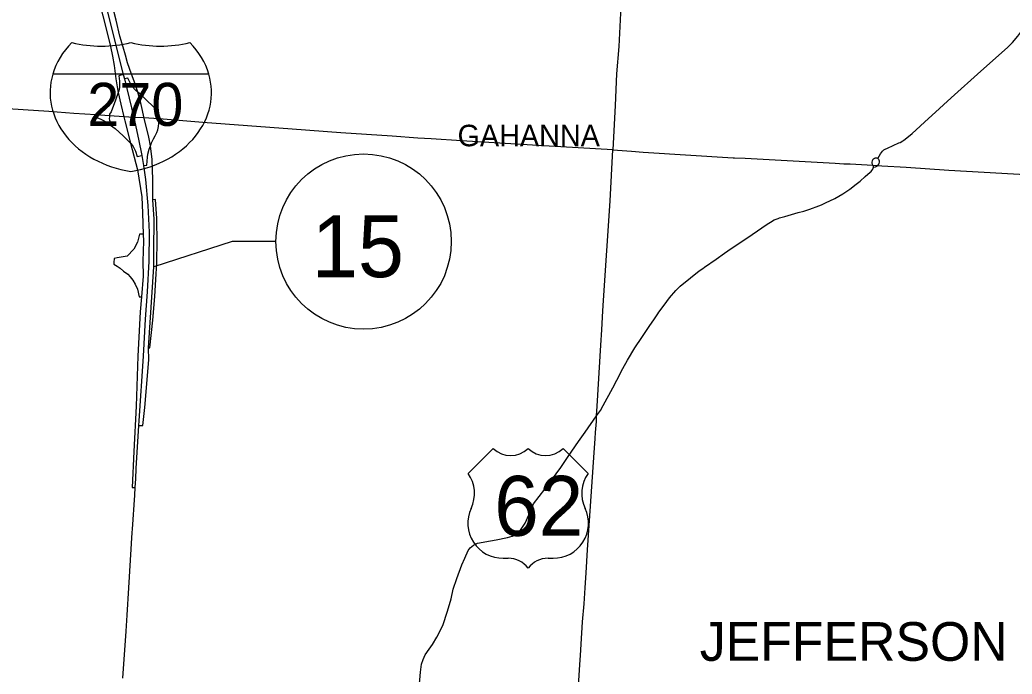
# Model space of a CAD drawing. Extents: x -1146 to -445, y -1283 to -822.
# Drawn here: x -822.8 to -765.1, y -1003.9 to -965.9 of the extents above; entities that cross this region are included whole.
import ezdxf

# ---------------------------------------------------------------- set-up
doc = ezdxf.new("R2010")
doc.units = 0
for name, color, linetype in [('Default', 7, 'Continuous'), ('GM_X_Corporation_Text', 7, 'Continuous'), ('GM_X_Interchange_Ramps', 7, 'Continuous'), ('GM_X_Interstate_Route', 7, 'Continuous'), ('GM_X_Interstate_Shield', 7, 'Continuous'), ('GM_X_Township', 7, 'Continuous'), ('GM_X_Township_Text', 7, 'Continuous'), ('GM_X_US_Route', 7, 'Continuous'), ('GM_X_US_Shield', 7, 'Continuous')]:
    doc.layers.add(name, color=color, linetype=linetype)

msp = doc.modelspace()

# ---------------------------------------------------------------- linework, layer by layer
at = {"layer": 'Default'}
msp.add_lwpolyline([(-807.904, -978.775), (-810.451, -978.775), (-814.999, -980.247)], dxfattribs=at)
msp.add_circle((-802.809, -978.775), 5.094, dxfattribs=at)
at = {"layer": 'GM_X_Interchange_Ramps'}
for points in [[(-818.434, -963.734), (-817.723, -966.557), (-817.506, -967.437), (-817.399, -967.988), (-817.306, -968.532), (-817.196, -969.313), (-817.127, -969.772), (-817.062, -970.115), (-816.912, -970.778), (-816.732, -971.52), (-816.687, -971.747), (-816.339, -973.048), (-815.949, -974.594), (-815.684, -976.167), (-815.643, -977.127), (-815.615, -978.352), (-815.601, -978.756), (-815.638, -979.921), (-815.614, -980.783), (-815.718, -981.989), (-815.786, -982.851), (-815.927, -985.431), (-816.027, -988.343), (-816.154, -990.973), (-816.259, -993.066), (-816.093, -993.075)], [(-815.875, -989.458), (-815.623, -989.471), (-815.511, -988.427), (-815.279, -985.64), (-815.308, -984.95), (-814.999, -980.247), (-814.995, -979.921), (-814.988, -979.307), (-814.971, -977.473), (-815.048, -976.349), (-815.05, -975.183), (-815.083, -974.007), (-815.196, -973.212), (-815.285, -972.704), (-815.56, -971.592), (-815.738, -970.811), (-815.928, -970.086), (-816.087, -969.609), (-816.284, -969.033), (-816.517, -968.381), (-816.647, -967.938), (-816.775, -967.471), (-816.96, -966.838), (-817.188, -965.901), (-817.841, -963.357)], [(-816.765, -969.055), (-817.021, -969.129), (-816.985, -969.452), (-816.992, -969.823), (-817.022, -970.003), (-817.062, -970.115), (-817.22, -970.548), (-817.481, -971.241), (-817.561, -971.372), (-817.568, -971.468)], [(-814.677, -971.641), (-814.679, -971.556), (-814.683, -971.4), (-814.709, -971.311), (-814.737, -971.24), (-814.78, -971.178), (-814.855, -971.099), (-815.02, -970.947), (-815.853, -970.152), (-815.928, -970.086), (-816.039, -969.991), (-816.274, -969.731), (-816.373, -969.551), (-816.453, -969.396), (-816.507, -969.266), (-816.7, -969.313)], [(-818.36, -971.403), (-818.369, -971.546), (-818.118, -971.638), (-817.88, -971.759), (-817.515, -971.997), (-817.248, -972.202), (-816.784, -972.631), (-816.339, -973.048), (-816.212, -973.216), (-816.057, -973.513), (-815.963, -973.821), (-815.699, -973.765)], [(-817.568, -971.468), (-817.572, -971.526), (-817.581, -971.63), (-817.575, -971.711), (-817.558, -971.778), (-817.522, -971.854), (-817.474, -971.946), (-817.515, -971.997)], [(-815.589, -974.345), (-815.401, -974.323), (-815.367, -973.872), (-815.338, -973.686), (-815.261, -973.399), (-815.196, -973.212), (-815.135, -973.036), (-815.011, -972.795), (-814.925, -972.628), (-814.826, -972.436), (-814.764, -972.281), (-814.714, -972.077), (-814.685, -971.743), (-814.677, -971.641)], [(-814.825, -979.927), (-814.822, -979.84), (-814.805, -978.876), (-814.828, -977.44), (-814.898, -976.336), (-815.048, -976.349)], [(-815.615, -978.352), (-815.824, -978.352), (-815.935, -978.812), (-816.158, -979.216), (-816.548, -979.619), (-817.12, -979.719), (-817.3, -979.763), (-817.31, -979.988)], [(-815.308, -984.95), (-815.219, -984.954), (-815.045, -983.338), (-814.935, -981.963), (-814.851, -980.645), (-814.828, -980.023), (-814.825, -979.927)], [(-817.31, -979.988), (-817.316, -980.093), (-817.128, -980.195), (-816.952, -980.314), (-816.758, -980.493), (-816.503, -980.669), (-816.362, -980.819), (-816.213, -981.018), (-816.077, -981.245), (-815.94, -981.545), (-815.854, -981.994), (-815.718, -981.989)]]:
    msp.add_lwpolyline(points, dxfattribs=at)
at = {"layer": 'GM_X_Interstate_Route'}
for points in [[(-818.092, -963.796), (-817.914, -964.494), (-816.765, -969.055), (-816.7, -969.313), (-816.158, -971.559)], [(-816.158, -971.559), (-815.89, -972.812), (-815.699, -973.765), (-815.589, -974.345), (-815.475, -975.162), (-815.333, -976.683), (-815.273, -978.231), (-815.28, -979.921), (-815.389, -981.688), (-815.488, -983.279), (-815.604, -985.435), (-815.858, -989.193)], [(-815.858, -989.193), (-815.875, -989.458), (-816.036, -991.971), (-816.066, -992.558)], [(-816.066, -992.558), (-816.093, -993.075), (-816.12, -993.525)], [(-816.12, -993.525), (-816.252, -995.495)], [(-816.252, -995.495), (-816.264, -995.684), (-816.461, -998.909)], [(-816.461, -998.909), (-816.557, -1000.485)], [(-816.557, -1000.485), (-816.614, -1001.423), (-816.811, -1004.161)]]:
    msp.add_lwpolyline(points, dxfattribs=at)
at = {"layer": 'GM_X_Interstate_Shield'}
msp.add_line((-811.801, -969.04), (-820.866, -969.04), dxfattribs=at)
msp.add_line((-811.801, -969.04), (-820.866, -969.04), dxfattribs=at)
for centre, start_param, end_param in [((-815.161, -970.112), 2.47259, 2.911027), ((-818.046, -962.722), 4.415841, 5.008937), ((-814.621, -962.722), 4.415841, 5.008937), ((-817.505, -970.112), 0.230566, 0.669003), ((-815.161, -970.112), 2.911027, 4.511031), ((-817.505, -970.112), 4.913747, 6.513751)]:
    msp.add_ellipse(centre, major_axis=(5.859, 0), ratio=0.8, start_param=start_param, end_param=end_param, dxfattribs=at)
at = {"layer": 'GM_X_Township'}
for points in [[(-787.857, -965.105), (-787.983, -967.439), (-788.122, -969.014), (-788.193, -970.867), (-788.336, -973.436), (-792.352, -973.212), (-797.126, -972.924), (-798.875, -972.805), (-799.656, -972.753), (-801.139, -972.649), (-804.137, -972.457), (-806.959, -972.237), (-812.147, -971.861), (-814.677, -971.641), (-815.587, -971.59), (-816.158, -971.559), (-816.732, -971.52), (-817.568, -971.468), (-818.36, -971.403), (-819.645, -971.332), (-821.102, -971.211), (-826.477, -970.87)], [(-790.477, -1007.136), (-790.244, -1003.355), (-790.203, -1002.844), (-790.167, -1002.179), (-790.095, -1000.889), (-790.001, -999.835), (-789.934, -998.899), (-789.876, -998.026), (-789.793, -996.691), (-789.434, -991.326), (-789.36, -990.221), (-789.334, -989.872), (-789.28, -989.226), (-789.273, -988.898), (-789.237, -988.352), (-789.026, -984.802), (-788.967, -983.902), (-788.903, -982.802), (-788.863, -982.202), (-788.479, -976.399), (-788.336, -973.436), (-787.238, -973.525), (-786.576, -973.585), (-781.335, -973.903), (-781.267, -973.898), (-780.649, -973.932), (-775.416, -974.224), (-774.915, -974.251), (-774.536, -974.263), (-773.235, -974.341), (-772.945, -974.358), (-772.698, -974.373), (-771.293, -974.457), (-768.805, -974.625), (-762.996, -974.951)]]:
    msp.add_lwpolyline(points, dxfattribs=at)
at = {"layer": 'GM_X_US_Route'}
for points in [[(-769.995, -971.616), (-769.805, -971.439), (-768.68, -970.417), (-766.961, -968.871), (-765.412, -967.488), (-765.108, -967.208), (-764.802, -966.833), (-764.638, -966.594), (-764.629, -966.573)], [(-771.476, -972.917), (-771.421, -972.887), (-771.248, -972.744), (-770.942, -972.5), (-769.995, -971.616)], [(-771.709, -973.039), (-771.645, -973.009), (-771.476, -972.917)], [(-772.932, -973.948), (-772.775, -973.681), (-772.727, -973.602), (-772.666, -973.526), (-772.582, -973.447), (-772.508, -973.398), (-772.378, -973.34), (-772.047, -973.197), (-771.709, -973.039)], [(-772.932, -973.948), (-772.976, -973.926), (-773.031, -973.917), (-773.082, -973.926), (-773.137, -973.953), (-773.187, -973.98), (-773.223, -974.012), (-773.267, -974.08), (-773.281, -974.156), (-773.278, -974.208)], [(-772.958, -974.366), (-772.945, -974.358), (-772.873, -974.28), (-772.854, -974.241), (-772.842, -974.163)], [(-772.842, -974.163), (-772.842, -974.161), (-772.846, -974.099), (-772.857, -974.037), (-772.876, -973.994), (-772.932, -973.948)], [(-774.197, -975.441), (-773.969, -975.27), (-773.662, -974.986), (-773.381, -974.744), (-773.326, -974.695), (-773.283, -974.648), (-773.23, -974.556), (-773.182, -974.447)], [(-773.278, -974.208), (-773.278, -974.216), (-773.265, -974.264), (-773.239, -974.331)], [(-773.239, -974.331), (-773.235, -974.341), (-773.182, -974.447)], [(-773.182, -974.447), (-773.07, -974.43), (-773, -974.394), (-772.958, -974.366)], [(-775.974, -976.529), (-775.435, -976.263), (-774.968, -975.99), (-774.567, -975.721), (-774.197, -975.441)], [(-780.244, -978.366), (-779.367, -977.76), (-779.176, -977.639), (-778.95, -977.519), (-778.73, -977.426), (-778.646, -977.403), (-778.338, -977.309), (-777.565, -977.085), (-777.243, -976.999), (-776.885, -976.885), (-776.372, -976.699), (-776.214, -976.631)], [(-776.214, -976.631), (-775.974, -976.529)], [(-781.449, -979.186), (-780.78, -978.737), (-780.244, -978.366)], [(-782.336, -979.793), (-781.851, -979.455), (-781.449, -979.186)], [(-782.997, -980.253), (-782.336, -979.793)], [(-785.95, -983.32), (-785.713, -982.97), (-785.651, -982.881), (-785.356, -982.48), (-785.029, -982.036), (-784.671, -981.612), (-784.415, -981.375), (-783.815, -980.875), (-783.322, -980.48), (-783.108, -980.33)], [(-783.108, -980.33), (-782.997, -980.253)], [(-786.174, -983.651), (-785.95, -983.32)], [(-788.099, -986.834), (-787.744, -986.161), (-787.484, -985.678), (-787.05, -984.944), (-786.641, -984.343), (-786.372, -983.944), (-786.174, -983.651)], [(-796.428, -996.419), (-796.183, -996.298), (-795.444, -996.162), (-795.102, -996.11), (-794.447, -995.981), (-794.186, -995.897), (-793.945, -995.768), (-793.726, -995.6), (-793.414, -995.145), (-793.079, -994.342), (-792.934, -994.03), (-792.273, -993.169), (-791.891, -992.645), (-791.341, -991.907), (-790.918, -991.278), (-790.328, -990.401), (-789.929, -989.862), (-789.273, -988.898), (-789.055, -988.588), (-788.89, -988.298), (-788.336, -987.272), (-788.099, -986.834)], [(-799.441, -1003.335), (-799.356, -1003.074), (-799.229, -1002.793), (-799.002, -1002.478), (-798.811, -1002.2), (-798.545, -1001.771), (-798.198, -1001.088), (-797.926, -1000.266), (-797.717, -999.548), (-797.607, -998.98), (-797.399, -998.366), (-797.092, -997.562), (-796.934, -997.174), (-796.729, -996.732), (-796.613, -996.58), (-796.428, -996.419)], [(-799.635, -1006.554), (-799.608, -1005.655), (-799.582, -1004.701), (-799.508, -1003.816), (-799.441, -1003.335)]]:
    msp.add_lwpolyline(points, dxfattribs=at)
at = {"layer": 'GM_X_US_Shield'}
for p, q in [((-795.28, -990.802), (-796.73, -992.252)), ((-789.769, -992.252), (-791.22, -990.802)), ((-794.7, -997.183), (-794.41, -997.183)), ((-792.09, -997.183), (-791.8, -997.183))]:
    msp.add_line(p, q, dxfattribs=at)
for centre, radius, start, end in [((-794.265, -989.766), 1.45, 225.573, 314.427), ((-792.235, -989.766), 1.45, 225.573, 314.427), ((-798.393, -993.417), 2.03, 334.54712, 35.00093), ((-788.106, -993.417), 2.03, 144.99907, 205.45288), ((-794.723, -995.153), 2.03, 154.83192, 270.63826), ((-791.777, -995.153), 2.03, 269.36174, 25.16808), ((-794.41, -998.633), 1.45, 36.8699, 90), ((-792.09, -998.633), 1.45, 90, 143.1301)]:
    msp.add_arc(centre, radius, start, end, dxfattribs=at)

# ---------------------------------------------------------------- texts
at = {"layer": 'Default'}
msp.add_text('15', height=3.6, dxfattribs=at).set_placement((-805.817, -980.844))
at = {"layer": 'GM_X_Corporation_Text'}
msp.add_text('GAHANNA', height=1.25, rotation=0.00001, dxfattribs=at).set_placement((-797.348, -973.233))
at = {"layer": 'GM_X_Interstate_Shield'}
msp.add_text('270', height=2.5, dxfattribs=at).set_placement((-818.858, -972.048))
at = {"layer": 'GM_X_Township_Text'}
msp.add_text('JEFFERSON', height=2.25, rotation=0.00001, dxfattribs=at).set_placement((-783.278, -1003.146))
at = {"layer": 'GM_X_US_Shield'}
msp.add_text('62', height=3.4805, dxfattribs=at).set_placement((-795.22, -995.877))

doc.saveas('drawing.dxf')
